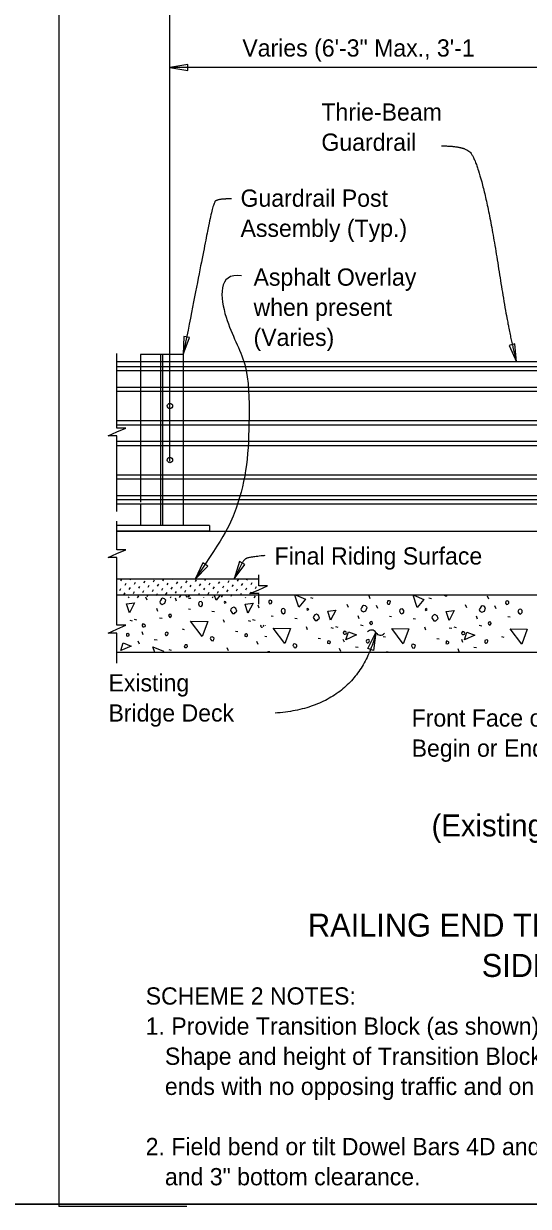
# Model space of a CAD drawing. Extents: x 0 to 41.1, y 0 to 25.9.
# Drawn here: x 18.69 to 24.59, y -0.02 to 13.8 of the extents above; entities that cross this region are included whole.
import ezdxf

# ---------------------------------------------------------------- set-up
doc = ezdxf.new("R2010")
doc.units = 0
for name, color, linetype in [('Dimension', 7, 'Continuous'), ('ExistSuperStruct', 7, 'Continuous'), ('Miscellaneous', 7, 'Continuous'), ('Miscellaneous1', 7, 'Continuous'), ('SteelMisc', 7, 'Continuous'), ('SteelMisc_h', 7, 'Continuous'), ('TextStructures', 7, 'Continuous')]:
    doc.layers.add(name, color=color, linetype=linetype)

msp = doc.modelspace()

# ---------------------------------------------------------------- linework, layer by layer
at = {"layer": 'Dimension'}
for p, q in [((19.1, 25.915), (19.1, -0.024)), ((31.932, 13.286), (20.399, 13.286)), ((20.596, -0.024), (19.1, -0.024))]:
    msp.add_line(p, q, dxfattribs=at)
for points in [[(0, 0), (41.051, 0), (41.051, 25.946), (0, 25.946)], [(20.399, 13.286), (20.607, 13.25), (20.607, 13.321)], [(20.555, 9.931), (20.63, 10.129), (20.56, 10.143)], [(24.45, 9.845), (24.432, 10.056), (24.364, 10.038)], [(20.694, 7.307), (20.841, 7.459), (20.783, 7.499)], [(21.151, 7.309), (21.275, 7.479), (21.212, 7.511)], [(22.808, 6.682), (22.778, 6.473), (22.711, 6.495)]]:
    msp.add_lwpolyline(points, close=True, dxfattribs=at)
for points in [[(19.779, 8.098), (19.779, 8.982), (19.676, 8.982), (19.779, 9.027), (19.882, 9.072), (19.779, 9.072), (19.779, 9.945)], [(19.779, 7.091), (19.779, 7.561), (19.676, 7.561), (19.779, 7.606), (19.882, 7.651), (19.779, 7.651), (19.779, 7.986)], [(21.437, 7.016), (21.437, 7.137), (21.334, 7.137), (21.437, 7.182), (21.54, 7.227), (21.437, 7.227), (21.437, 7.358)], [(19.779, 6.326), (19.779, 6.677), (19.676, 6.677), (19.779, 6.722), (19.882, 6.767), (19.779, 6.767), (19.779, 7.091)]]:
    msp.add_lwpolyline(points, dxfattribs=at)
for centre, start, end in [((22.756, 6.652), 30.0081, 141.7354), ((22.859, 6.712), 210.0081, 321.7354)]:
    msp.add_arc(centre, 0.0596, start, end, dxfattribs=at)
for points, degree in [([(23.574, 12.37), (23.842, 12.37), (23.977, 12.221), (24.153, 11.514), (24.351, 10.227), (24.45, 9.845)], 2), ([(21.12, 11.751), (20.957, 11.751), (20.904, 11.698), (20.806, 11.211), (20.555, 9.931)], 2), ([(21.238, 10.852), (20.951, 10.893), (21.024, 10.293), (21.322, 9.854), (21.328, 9.18), (21.311, 8.638), (21.191, 8.129), (21.045, 7.817), (20.694, 7.307)], 3), ([(21.507, 7.581), (21.333, 7.566), (21.259, 7.534), (21.194, 7.394), (21.151, 7.309)], 2), ([(22.808, 6.682), (22.588, 5.808), (21.628, 5.74)], 2)]:
    msp.add_open_spline(points, degree=degree, dxfattribs=at)
at = {"layer": 'ExistSuperStruct'}
for p, q in [((19.779, 7.869), (27.563, 7.869)), ((21.437, 7.307), (19.779, 7.307)), ((27.563, 7.119), (19.779, 7.119)), ((19.779, 6.452), (27.563, 6.452))]:
    msp.add_line(p, q, dxfattribs=at)
at = {"layer": 'Miscellaneous'}
for p, q in [((20.399, 8.681), (20.399, 15.38)), ((19.813, 7.174), (19.826, 7.197)), ((19.826, 7.285), (19.839, 7.307)), ((19.875, 7.236), (19.888, 7.258)), ((19.924, 7.187), (19.937, 7.209)), ((19.937, 7.298), (19.942, 7.307)), ((19.985, 7.249), (19.998, 7.271)), ((20.034, 7.2), (20.047, 7.222)), ((20.096, 7.262), (20.109, 7.284)), ((20.145, 7.213), (20.158, 7.235)), ((20.207, 7.275), (20.22, 7.297)), ((20.256, 7.226), (20.268, 7.248)), ((20.304, 7.177), (20.317, 7.2)), ((20.317, 7.288), (20.329, 7.307)), ((20.366, 7.239), (20.379, 7.261)), ((20.415, 7.19), (20.428, 7.213)), ((20.428, 7.301), (20.432, 7.307)), ((20.477, 7.252), (20.49, 7.274)), ((20.526, 7.203), (20.539, 7.225)), ((20.587, 7.265), (20.6, 7.287)), ((20.636, 7.216), (20.649, 7.238)), ((20.685, 7.167), (20.698, 7.19)), ((20.698, 7.278), (20.711, 7.3)), ((20.747, 7.229), (20.76, 7.251)), ((20.796, 7.18), (20.809, 7.203)), ((20.809, 7.291), (20.818, 7.307)), ((20.858, 7.242), (20.87, 7.264)), ((20.906, 7.193), (20.919, 7.216)), ((20.919, 7.304), (20.921, 7.307)), ((20.968, 7.255), (20.981, 7.277)), ((21.017, 7.206), (21.03, 7.229)), ((21.079, 7.268), (21.092, 7.29)), ((21.128, 7.219), (21.141, 7.241)), ((21.176, 7.17), (21.189, 7.193)), ((21.189, 7.281), (21.202, 7.303)), ((21.238, 7.232), (21.251, 7.254)), ((21.287, 7.183), (21.3, 7.206)), ((21.3, 7.294), (21.308, 7.307)), ((21.349, 7.245), (21.362, 7.267)), ((21.398, 7.196), (21.411, 7.219)), ((21.411, 7.307), (21.411, 7.307)), ((19.862, 7.125), (19.875, 7.148)), ((19.917, 7.088), (19.924, 7.099)), ((19.972, 7.138), (19.985, 7.161)), ((20.021, 7.089), (20.034, 7.112)), ((20.083, 7.151), (20.096, 7.174)), ((20.133, 7.061), (20.119, 7.096)), ((20.132, 7.102), (20.145, 7.125)), ((20.194, 7.164), (20.207, 7.187)), ((20.243, 7.115), (20.256, 7.138)), ((20.304, 7.088), (20.304, 7.089)), ((20.353, 7.128), (20.366, 7.151)), ((20.407, 7.088), (20.415, 7.102)), ((20.477, 7.049), (20.463, 7.084)), ((20.464, 7.141), (20.477, 7.164)), ((20.513, 7.092), (20.526, 7.115)), ((20.574, 7.154), (20.587, 7.177)), ((20.623, 7.105), (20.636, 7.128)), ((20.734, 7.118), (20.747, 7.141)), ((20.794, 7.088), (20.796, 7.092)), ((20.845, 7.131), (20.858, 7.154)), ((20.897, 7.088), (20.906, 7.105)), ((20.955, 7.144), (20.968, 7.167)), ((21.004, 7.095), (21.017, 7.118)), ((21.066, 7.157), (21.079, 7.18)), ((21.115, 7.108), (21.128, 7.131)), ((21.225, 7.121), (21.238, 7.144)), ((21.283, 7.088), (21.287, 7.095)), ((21.336, 7.134), (21.349, 7.157)), ((21.386, 7.088), (21.398, 7.108)), ((21.447, 7.147), (21.447, 7.148)), ((22.043, 7.092), (22.071, 7.085)), ((22.741, 7.076), (22.727, 7.111)), ((23.427, 7.088), (23.456, 7.081)), ((24.126, 7.072), (24.111, 7.108)), ((20.258, 6.928), (20.246, 6.962)), ((20.615, 6.961), (20.64, 6.957)), ((20.891, 6.932), (20.921, 6.927)), ((21.444, 6.967), (21.43, 7.002)), ((22.485, 6.975), (22.47, 7.01)), ((22.829, 6.963), (22.814, 6.999)), ((23.869, 6.972), (23.855, 7.007)), ((24.213, 6.96), (24.199, 6.995)), ((19.929, 6.828), (19.957, 6.821)), ((19.981, 6.838), (20.009, 6.831)), ((20.277, 6.856), (20.307, 6.851)), ((21.039, 6.798), (21.027, 6.831)), ((21.313, 6.824), (21.341, 6.817)), ((21.366, 6.834), (21.394, 6.827)), ((21.582, 6.879), (21.607, 6.875)), ((21.858, 6.85), (21.888, 6.845)), ((22.61, 6.843), (22.598, 6.876)), ((22.967, 6.875), (22.991, 6.871)), ((23.242, 6.847), (23.272, 6.841)), ((23.995, 6.839), (23.982, 6.873)), ((24.351, 6.871), (24.376, 6.868)), ((20.087, 6.655), (20.075, 6.689)), ((20.541, 6.724), (20.567, 6.718)), ((21.166, 6.699), (21.193, 6.694)), ((21.508, 6.642), (21.534, 6.636)), ((22.006, 6.716), (21.994, 6.749)), ((22.28, 6.742), (22.308, 6.735)), ((22.333, 6.752), (22.361, 6.745)), ((22.629, 6.771), (22.659, 6.765)), ((22.892, 6.638), (22.919, 6.633)), ((23.391, 6.712), (23.378, 6.746)), ((23.665, 6.739), (23.693, 6.732)), ((23.717, 6.749), (23.745, 6.742)), ((24.014, 6.767), (24.044, 6.762)), ((20.045, 6.546), (20.03, 6.581)), ((20.217, 6.602), (20.249, 6.598)), ((21.083, 6.467), (21.069, 6.503)), ((21.429, 6.542), (21.415, 6.578)), ((22.133, 6.617), (22.16, 6.612)), ((22.439, 6.57), (22.426, 6.603)), ((22.569, 6.516), (22.601, 6.513)), ((23.518, 6.613), (23.545, 6.608)), ((23.823, 6.566), (23.811, 6.6)), ((23.953, 6.513), (23.985, 6.509)), ((24.277, 6.635), (24.303, 6.629)), ((20.385, 6.483), (20.413, 6.476)), ((22.396, 6.46), (22.382, 6.496)), ((23.781, 6.457), (23.767, 6.492))]:
    msp.add_line(p, q, dxfattribs=at)
for points in [[(20.287, 7.024), (20.31, 7.011), (20.34, 7.024), (20.352, 7.061), (20.334, 7.078), (20.311, 7.084), (20.301, 7.077), (20.288, 7.057), (20.28, 7.041), (20.287, 7.024)], [(20.587, 7.116), (20.595, 7.1), (20.615, 7.102), (20.624, 7.114), (20.624, 7.116)], [(20.619, 7.088), (20.62, 7.086), (20.618, 7.088)], [(20.62, 7.086), (20.641, 7.086), (20.644, 7.088)], [(20.938, 7.061), (20.921, 7.116)], [(20.984, 7.116), (20.938, 7.061)], [(21.554, 7.034), (21.562, 7.018), (21.582, 7.02), (21.591, 7.032), (21.592, 7.052), (21.58, 7.057), (21.571, 7.059), (21.561, 7.055), (21.557, 7.052), (21.554, 7.034)], [(21.905, 6.979), (21.86, 7.119)], [(21.874, 7.119), (21.983, 7.071), (21.905, 6.979)], [(22.938, 7.031), (22.947, 7.015), (22.967, 7.016), (22.975, 7.029), (22.977, 7.048), (22.965, 7.054), (22.956, 7.055), (22.945, 7.052), (22.942, 7.048), (22.938, 7.031)], [(23.29, 6.976), (23.243, 7.119)], [(23.25, 7.119), (23.368, 7.068), (23.29, 6.976)], [(23.612, 7.119), (23.615, 7.113), (23.611, 7.117)], [(23.615, 7.113), (23.636, 7.113), (23.642, 7.119)], [(24.323, 7.027), (24.332, 7.011), (24.351, 7.013), (24.36, 7.025), (24.362, 7.045), (24.349, 7.05), (24.341, 7.052), (24.33, 7.048), (24.326, 7.045), (24.323, 7.027)], [(19.926, 6.914), (19.893, 7.018), (19.986, 7.031), (19.926, 6.914)], [(20.732, 7.017), (20.742, 6.996), (20.76, 6.985), (20.774, 6.996), (20.781, 7.006), (20.781, 7.028), (20.765, 7.044), (20.746, 7.042), (20.737, 7.033), (20.732, 7.017)], [(21.037, 7.026), (21.057, 7.035), (21.05, 7.042), (21.037, 7.047), (21.032, 7.035), (21.037, 7.026)], [(21.108, 6.941), (21.131, 6.904), (21.154, 6.906), (21.163, 6.915), (21.182, 6.934), (21.17, 6.964), (21.145, 6.978), (21.128, 6.971), (21.113, 6.957), (21.108, 6.941)], [(21.311, 6.91), (21.277, 7.015), (21.371, 7.027), (21.311, 6.91)], [(21.699, 6.935), (21.709, 6.914), (21.727, 6.903), (21.741, 6.914), (21.748, 6.924), (21.748, 6.946), (21.732, 6.962), (21.713, 6.96), (21.704, 6.951), (21.699, 6.935)], [(22.004, 6.944), (22.024, 6.953), (22.017, 6.96), (22.004, 6.965), (21.999, 6.953), (22.004, 6.944)], [(22.278, 6.828), (22.244, 6.933), (22.338, 6.945), (22.278, 6.828)], [(22.638, 6.938), (22.661, 6.926), (22.691, 6.938), (22.704, 6.975), (22.686, 6.993), (22.663, 6.998), (22.652, 6.991), (22.64, 6.972), (22.631, 6.956), (22.638, 6.938)], [(23.083, 6.932), (23.094, 6.91), (23.111, 6.9), (23.126, 6.91), (23.133, 6.921), (23.133, 6.942), (23.117, 6.958), (23.097, 6.956), (23.088, 6.947), (23.083, 6.932)], [(23.389, 6.94), (23.408, 6.949), (23.401, 6.956), (23.389, 6.962), (23.384, 6.949), (23.389, 6.94)], [(23.662, 6.825), (23.629, 6.929), (23.722, 6.942), (23.662, 6.825)], [(24.023, 6.934), (24.046, 6.922), (24.076, 6.934), (24.088, 6.972), (24.071, 6.989), (24.048, 6.995), (24.037, 6.987), (24.025, 6.968), (24.016, 6.952), (24.023, 6.934)], [(24.468, 6.928), (24.478, 6.907), (24.496, 6.896), (24.51, 6.907), (24.517, 6.917), (24.517, 6.939), (24.501, 6.955), (24.482, 6.953), (24.473, 6.944), (24.468, 6.928)], [(20.083, 6.75), (20.096, 6.748), (20.108, 6.753), (20.112, 6.764), (20.106, 6.772), (20.096, 6.78), (20.083, 6.785), (20.076, 6.771), (20.073, 6.76), (20.083, 6.75)], [(20.389, 6.869), (20.399, 6.858), (20.41, 6.865), (20.417, 6.876), (20.413, 6.893), (20.405, 6.895), (20.392, 6.893), (20.382, 6.883), (20.389, 6.869)], [(20.776, 6.637), (20.641, 6.814), (20.841, 6.812), (20.776, 6.637)], [(22.075, 6.859), (22.098, 6.822), (22.121, 6.824), (22.13, 6.833), (22.149, 6.852), (22.137, 6.882), (22.112, 6.896), (22.094, 6.889), (22.08, 6.875), (22.075, 6.859)], [(22.74, 6.783), (22.751, 6.772), (22.761, 6.78), (22.769, 6.79), (22.765, 6.808), (22.756, 6.81), (22.744, 6.808), (22.733, 6.797), (22.74, 6.783)], [(23.46, 6.856), (23.483, 6.818), (23.506, 6.82), (23.515, 6.829), (23.534, 6.848), (23.522, 6.879), (23.497, 6.893), (23.479, 6.886), (23.465, 6.871), (23.46, 6.856)], [(24.125, 6.78), (24.136, 6.769), (24.146, 6.776), (24.153, 6.787), (24.15, 6.804), (24.141, 6.806), (24.128, 6.804), (24.118, 6.794), (24.125, 6.78)], [(19.89, 6.644), (19.909, 6.639), (19.921, 6.648), (19.923, 6.66), (19.92, 6.664), (19.906, 6.671), (19.893, 6.669), (19.891, 6.656), (19.89, 6.644)], [(20.353, 6.649), (20.36, 6.649), (20.374, 6.656), (20.38, 6.672), (20.378, 6.681), (20.364, 6.688), (20.346, 6.678), (20.343, 6.667), (20.346, 6.656), (20.353, 6.649)], [(21.274, 6.641), (21.294, 6.635), (21.306, 6.644), (21.308, 6.656), (21.304, 6.66), (21.29, 6.667), (21.278, 6.665), (21.276, 6.653), (21.274, 6.641)], [(21.462, 6.77), (21.461, 6.767), (21.458, 6.757), (21.468, 6.746)], [(21.468, 6.746), (21.48, 6.744), (21.482, 6.745)], [(21.494, 6.752), (21.496, 6.76), (21.491, 6.769), (21.49, 6.77)], [(21.517, 6.766), (21.518, 6.77)], [(21.743, 6.555), (21.608, 6.732), (21.808, 6.73), (21.743, 6.555)], [(22.435, 6.664), (22.447, 6.662), (22.46, 6.668), (22.463, 6.678), (22.458, 6.687), (22.447, 6.694), (22.435, 6.699), (22.428, 6.685), (22.424, 6.675), (22.435, 6.664)], [(22.457, 6.599), (22.486, 6.691), (22.579, 6.654), (22.457, 6.599)], [(23.127, 6.551), (22.993, 6.728), (23.193, 6.726), (23.127, 6.551)], [(23.82, 6.66), (23.832, 6.659), (23.844, 6.664), (23.848, 6.675), (23.843, 6.683), (23.832, 6.69), (23.82, 6.696), (23.813, 6.682), (23.809, 6.671), (23.82, 6.66)], [(23.842, 6.596), (23.87, 6.688), (23.964, 6.65), (23.842, 6.596)], [(24.512, 6.548), (24.378, 6.725), (24.577, 6.723), (24.512, 6.548)], [(19.825, 6.471), (19.853, 6.562), (19.947, 6.525), (19.825, 6.471)], [(20.222, 6.449), (20.2, 6.517), (20.326, 6.463), (20.314, 6.449)], [(20.572, 6.508), (20.594, 6.508), (20.604, 6.519), (20.599, 6.538), (20.576, 6.54), (20.572, 6.529), (20.567, 6.52), (20.572, 6.508), (20.569, 6.511)], [(20.875, 6.605), (20.884, 6.589), (20.905, 6.586), (20.914, 6.602), (20.917, 6.616), (20.908, 6.625), (20.892, 6.633), (20.877, 6.628), (20.871, 6.612), (20.875, 6.605)], [(21.842, 6.523), (21.851, 6.507), (21.872, 6.504), (21.881, 6.52), (21.884, 6.534), (21.875, 6.543), (21.859, 6.551), (21.843, 6.546), (21.838, 6.53), (21.842, 6.523)], [(22.241, 6.559), (22.261, 6.553), (22.273, 6.562), (22.275, 6.574), (22.271, 6.578), (22.257, 6.585), (22.245, 6.583), (22.243, 6.571), (22.241, 6.559)], [(22.705, 6.564), (22.712, 6.564), (22.726, 6.571), (22.731, 6.587), (22.73, 6.596), (22.715, 6.603), (22.698, 6.592), (22.694, 6.582), (22.698, 6.571), (22.705, 6.564)], [(23.226, 6.52), (23.235, 6.504), (23.256, 6.5), (23.265, 6.516), (23.269, 6.53), (23.26, 6.539), (23.244, 6.548), (23.228, 6.543), (23.223, 6.527), (23.226, 6.52)], [(23.626, 6.555), (23.645, 6.55), (23.658, 6.559), (23.659, 6.571), (23.656, 6.574), (23.642, 6.582), (23.629, 6.58), (23.628, 6.567), (23.626, 6.555)], [(24.09, 6.56), (24.097, 6.56), (24.111, 6.567), (24.116, 6.583), (24.114, 6.592), (24.1, 6.599), (24.082, 6.589), (24.079, 6.578), (24.082, 6.567), (24.09, 6.56)], [(19.92, 6.449), (19.914, 6.45), (19.91, 6.449)], [(21.567, 6.452), (21.566, 6.456), (21.543, 6.458), (21.541, 6.452)], [(22.951, 6.452), (22.951, 6.452), (22.928, 6.454), (22.927, 6.452)]]:
    msp.add_lwpolyline(points, dxfattribs=at)
at = {"layer": 'Miscellaneous1'}
msp.add_lwpolyline([(0, 25.946), (41.051, 25.946), (41.051, 0), (0, 0)], close=True, dxfattribs=at)
at = {"layer": 'SteelMisc'}
for p, q in [((26.232, 9.848), (19.779, 9.848)), ((20.555, 9.931), (20.055, 9.931)), ((20.055, 9.931), (20.055, 9.848)), ((20.555, 9.931), (20.555, 9.848)), ((19.779, 9.793), (26.232, 9.793)), ((19.779, 9.744), (26.232, 9.744)), ((19.779, 9.552), (26.232, 9.552)), ((19.779, 9.503), (26.232, 9.503)), ((19.779, 9.159), (26.232, 9.159)), ((19.779, 9.111), (26.232, 9.111)), ((19.779, 8.918), (26.232, 8.918)), ((19.779, 8.87), (26.232, 8.87)), ((19.779, 8.526), (26.232, 8.526)), ((19.779, 8.478), (26.232, 8.478)), ((19.779, 8.285), (26.232, 8.285)), ((19.779, 8.237), (26.232, 8.237)), ((26.232, 8.181), (19.779, 8.181)), ((20.055, 8.181), (20.055, 7.932)), ((20.555, 8.181), (20.555, 7.932)), ((20.862, 7.932), (19.779, 7.932)), ((20.555, 7.932), (20.055, 7.932)), ((20.862, 7.932), (20.862, 7.869)), ((20.862, 7.869), (19.779, 7.869))]:
    msp.add_line(p, q, dxfattribs=at)
for centre in [(20.399, 9.331), (20.399, 8.698)]:
    msp.add_circle(centre, 0.0312, dxfattribs=at)
at = {"layer": 'SteelMisc_h'}
for p, q in [((20.055, 9.848), (20.055, 8.205)), ((20.294, 7.932), (20.294, 9.931)), ((20.315, 7.932), (20.315, 9.931)), ((20.555, 9.848), (20.555, 8.181))]:
    msp.add_line(p, q, dxfattribs=at)

# ---------------------------------------------------------------- texts
at = {"layer": 'Dimension'}
for s, height, p in [('Thrie-Beam ', 0.2016, (22.17, 12.665)), ('Guardrail', 0.2016, (22.17, 12.313)), ('Guardrail Post ', 0.2016, (21.225, 11.659)), ('Assembly (Typ.)', 0.2016, (21.225, 11.307)), ('Asphalt Overlay', 0.2016, (21.377, 10.736)), ('when present', 0.2016, (21.377, 10.384)), ('(Varies)', 0.2016, (21.377, 10.032)), ('Existing ', 0.2016, (19.681, 5.994)), ('Bridge Deck', 0.2016, (19.681, 5.642)), ('Front Face of Backwall &', 0.2016, (23.225, 5.583)), ('Begin or End Bridge', 0.2016, (23.225, 5.231)), ('(Existing Wing Post and Traffic Railing not shown for clarity)', 0.256, (23.458, 4.3)), ('RAILING END TREATMENT FOR PARALLEL OR FLARED CURBS WITH DETACHED', 0.2688, (22.013, 3.128)), ('SIDEWALKS OR INTEGRAL SIDEWALK LESS THAN 6" THICK', 0.2688, (24.044, 2.657)), ('SCHEME 2 NOTES:', 0.2016, (20.116, 2.334)), ('1. Provide Transition Block (as shown) or Curb if existing Approach Slab Curb does not extend to end of Approach Slab.  ', 0.2016, (20.116, 1.982)), ('   Shape and height of Transition Block or Curb shall match existing bridge curb.  Transition Block may be omitted on trailing ', 0.2016, (20.116, 1.63)), ('   ends with no opposing traffic and on bridges with flared Approach Slab Curbs.', 0.2016, (20.116, 1.278)), ('2. Field bend or tilt Dowel Bars 4D and Bars 4M within Transition Block as required to maintain 2" top and side clearance ', 0.2016, (20.116, 0.574)), ('   and 3" bottom clearance.', 0.2016, (20.116, 0.222))]:
    msp.add_text(s, height=height, dxfattribs=at).set_placement(p)
at = {"layer": 'TextStructures'}
for s, p in [('Varies (6\'-3" Max., 3\'-1', (21.246, 13.414)), ('Final Riding Surface', (21.623, 7.477))]:
    msp.add_text(s, height=0.2016, dxfattribs=at).set_placement(p)

doc.saveas('drawing.dxf')
